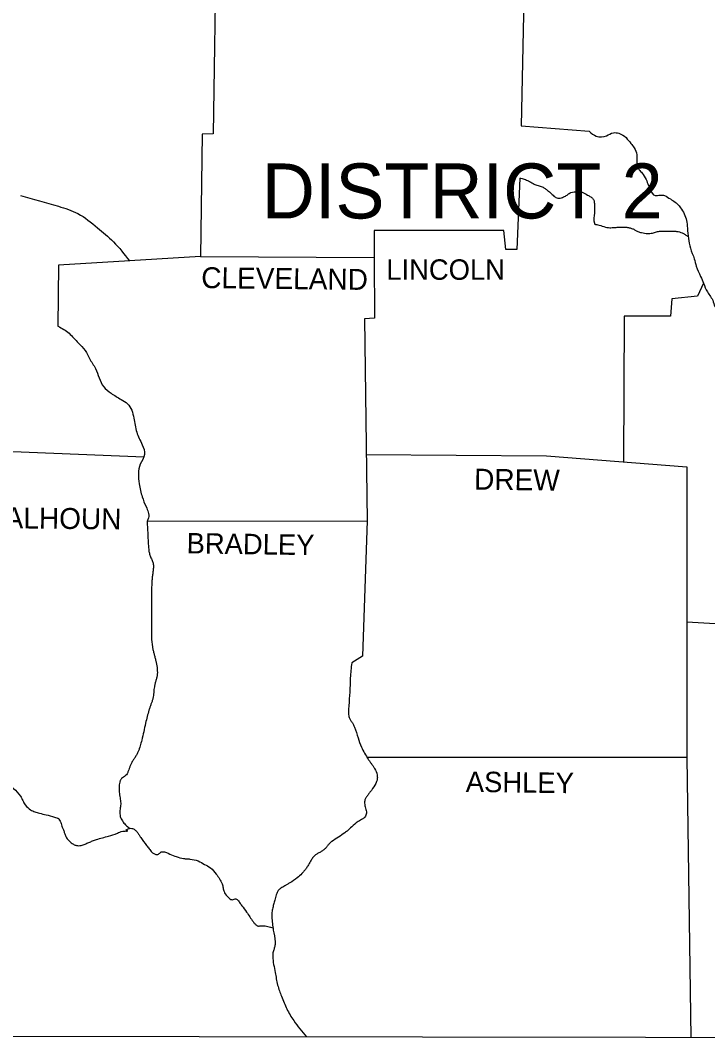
# Model space of a CAD drawing. Extents: x 1334737.7 to 1334827.2, y 402732.3 to 402753.5.
# Drawn here: x 1334764.914 to 1334766.509, y 402745.105 to 402747.469 of the extents above; entities that cross this region are included whole.
import ezdxf

# ---------------------------------------------------------------- set-up
doc = ezdxf.new("R2010")
doc.units = 0
doc.layers.add('Default', color=7, linetype='Continuous')

msp = doc.modelspace()

# ---------------------------------------------------------------- linework, layer by layer
at = {"layer": 'Default'}
for points in [[(1334765.3686, 402747.6648), (1334765.3618, 402747.2056), (1334765.3358, 402747.2045), (1334765.3324, 402746.9205)], [(1334766.0861, 402747.6676), (1334766.0767, 402747.2237), (1334766.234, 402747.2112)], [(1334766.0733, 402747.1027), (1334766.0665, 402746.9364), (1334766.0405, 402746.9364), (1334766.036, 402746.9805), (1334765.7351, 402746.9805), (1334765.7355, 402746.9183)], [(1334765.1677, 402746.9104), (1334765.0021, 402746.9002), (1334765.001, 402746.7588)], [(1334765.3324, 402746.9205), (1334765.167, 402746.9103)], [(1334765.3324, 402746.9205), (1334765.7355, 402746.9183)], [(1334765.7355, 402746.9183), (1334765.7362, 402746.7769), (1334765.7125, 402746.7758), (1334765.7193, 402746.3063)], [(1334766.4998, 402746.8583), (1334766.4862, 402746.8278), (1334766.4262, 402746.8221), (1334766.4229, 402746.7814), (1334766.3154, 402746.7814), (1334766.3143, 402746.4432)], [(1334764.3698, 402746.4862), (1334764.8381, 402746.4692), (1334765.2014, 402746.455)], [(1334765.7159, 402746.4602), (1334766.1355, 402746.4568), (1334766.4613, 402746.4319)], [(1334766.4613, 402746.4319), (1334766.4613, 402745.7555), (1334766.4704, 402745.1058)], [(1334765.208, 402746.3052), (1334765.7193, 402746.3063)], [(1334765.7193, 402746.3063), (1334765.708, 402745.9919), (1334765.6831, 402745.9761)], [(1334766.4613, 402746.0714), (1334766.6185, 402746.062), (1334766.6253, 402745.9964), (1334766.7622, 402746.0009), (1334766.7679, 402746.0564), (1334766.8102, 402746.0564)], [(1334762.7353, 402746.027), (1334762.7376, 402745.1119), (1334766.8832, 402745.1051)], [(1334765.7187, 402745.7566), (1334766.4613, 402745.7566)]]:
    msp.add_lwpolyline(points, dxfattribs=at)
for points in [[(1334766.234, 402747.2112), (1334766.2509, 402747.1999), (1334766.2747, 402747.2011), (1334766.2905, 402747.2078), (1334766.303, 402747.2067), (1334766.3199, 402747.1965), (1334766.3312, 402747.183), (1334766.3391, 402747.1728), (1334766.3448, 402747.1569), (1334766.3448, 402747.1422), (1334766.3505, 402747.1219), (1334766.3572, 402747.114), (1334766.3663, 402747.0993), (1334766.372, 402747.0857), (1334766.3753, 402747.0766), (1334766.3878, 402747.0619), (1334766.3991, 402747.0631), (1334766.4093, 402747.0619), (1334766.4229, 402747.054), (1334766.4432, 402747.0382), (1334766.4466, 402747.0337), (1334766.4602, 402747.0042), (1334766.4624, 402746.9861), (1334766.4647, 402746.9624), (1334766.4692, 402746.9398), (1334766.4783, 402746.9149), (1334766.4828, 402746.8979), (1334766.493, 402746.8742), (1334766.4998, 402746.8583), (1334766.5088, 402746.838), (1334766.5224, 402746.8153), (1334766.528, 402746.8018), (1334766.5473, 402746.8029), (1334766.5609, 402746.8086), (1334766.571, 402746.8176), (1334766.5835, 402746.8165), (1334766.597, 402746.812), (1334766.6151, 402746.8086), (1334766.6265, 402746.8153), (1334766.6321, 402746.8199), (1334766.6332, 402746.8301), (1334766.6434, 402746.8357), (1334766.6547, 402746.8278), (1334766.6672, 402746.8097), (1334766.6672, 402746.7984), (1334766.6627, 402746.7916), (1334766.648, 402746.7825), (1334766.6276, 402746.7758), (1334766.6219, 402746.7678), (1334766.6412, 402746.7588), (1334766.6717, 402746.7565), (1334766.6796, 402746.7633), (1334766.7, 402746.7577), (1334766.7079, 402746.7633), (1334766.7351, 402746.7622), (1334766.7475, 402746.7712), (1334766.7724, 402746.7701), (1334766.7803, 402746.7644), (1334766.7803, 402746.7543), (1334766.8007, 402746.7497), (1334766.8154, 402746.7531), (1334766.8346, 402746.7475), (1334766.8516, 402746.7384), (1334766.8606, 402746.726), (1334766.8719, 402746.7124), (1334766.8821, 402746.7158), (1334766.89, 402746.726), (1334766.907, 402746.7441), (1334766.907, 402746.7554), (1334766.9115, 402746.7633), (1334766.9183, 402746.778)], [(1334766.0733, 402747.1027), (1334766.0786, 402747.1016), (1334766.0837, 402747.1), (1334766.0937, 402747.0959), (1334766.0974, 402747.094), (1334766.1011, 402747.0919), (1334766.1047, 402747.0898), (1334766.1084, 402747.0879), (1334766.1132, 402747.0862), (1334766.1181, 402747.0848), (1334766.123, 402747.0833), (1334766.1276, 402747.0812), (1334766.134, 402747.0768), (1334766.1401, 402747.0721), (1334766.1443, 402747.0685), (1334766.1485, 402747.0646), (1334766.1526, 402747.0608), (1334766.1548, 402747.059), (1334766.157, 402747.0574), (1334766.1617, 402747.0558), (1334766.167, 402747.0561), (1334766.1724, 402747.0577), (1334766.1774, 402747.0597), (1334766.1811, 402747.0618), (1334766.1846, 402747.0644), (1334766.1881, 402747.0669), (1334766.1921, 402747.0687), (1334766.2068, 402747.071), (1334766.2181, 402747.0698), (1334766.2306, 402747.0631), (1334766.2379, 402747.0589), (1334766.2413, 402747.0563), (1334766.2428, 402747.0547), (1334766.2435, 402747.0539), (1334766.2441, 402747.0529), (1334766.2463, 402747.0456), (1334766.2464, 402747.0419), (1334766.2464, 402747.0382), (1334766.2464, 402747.0212), (1334766.2464, 402746.9975), (1334766.2472, 402746.9958), (1334766.2493, 402746.995), (1334766.2543, 402746.9941), (1334766.2684, 402746.9897), (1334766.2826, 402746.9873), (1334766.2874, 402746.9874), (1334766.2922, 402746.9877), (1334766.297, 402746.9881), (1334766.3018, 402746.9884), (1334766.3109, 402746.9886), (1334766.3199, 402746.9884), (1334766.3274, 402746.9873), (1334766.331, 402746.9863), (1334766.3346, 402746.985), (1334766.3378, 402746.9835), (1334766.3408, 402746.9815), (1334766.3438, 402746.9797), (1334766.3471, 402746.9782), (1334766.3561, 402746.976), (1334766.3697, 402746.9737), (1334766.381, 402746.9748), (1334766.3858, 402746.976), (1334766.3906, 402746.9775), (1334766.3954, 402746.9788), (1334766.4002, 402746.9794), (1334766.4115, 402746.9794), (1334766.4296, 402746.9794), (1334766.4353, 402746.979), (1334766.4381, 402746.9786), (1334766.441, 402746.9782), (1334766.453, 402746.9737), (1334766.4588, 402746.9702), (1334766.4643, 402746.9665)], [(1334764.9139, 402747.0619), (1334765.0021, 402747.037), (1334765.0474, 402747.0201), (1334765.0926, 402746.9873), (1334765.1299, 402746.9545), (1334765.167, 402746.9103)], [(1334765.001, 402746.7588), (1334765.027, 402746.7418), (1334765.0485, 402746.7192), (1334765.0643, 402746.7022), (1334765.0745, 402746.683), (1334765.0881, 402746.6604), (1334765.1073, 402746.6174), (1334765.1243, 402746.6027), (1334765.148, 402746.588), (1334765.1628, 402746.5778), (1334765.1775, 402746.545), (1334765.1842, 402746.5122), (1334765.1967, 402746.4828), (1334765.2023, 402746.4602), (1334765.1922, 402746.4376), (1334765.1899, 402746.3923), (1334765.1967, 402746.3618), (1334765.2057, 402746.3391), (1334765.2114, 402746.3131), (1334765.208, 402746.3052)], [(1334765.208, 402746.3052), (1334765.2089, 402746.2877), (1334765.2099, 402746.2701), (1334765.2125, 402746.2351), (1334765.2145, 402746.2265), (1334765.218, 402746.2181), (1334765.2213, 402746.2097), (1334765.2223, 402746.2055), (1334765.2227, 402746.2011), (1334765.2222, 402746.1921), (1334765.2211, 402746.1831), (1334765.22, 402746.174), (1334765.2193, 402746.165), (1334765.2182, 402746.1299), (1334765.2182, 402746.0982), (1334765.2182, 402746.0677), (1334765.2182, 402746.036), (1334765.2204, 402746.0134), (1334765.2221, 402746.0051), (1334765.2242, 402745.9969), (1334765.2264, 402745.9888), (1334765.2284, 402745.9806), (1334765.2311, 402745.9653), (1334765.2318, 402745.9576), (1334765.2318, 402745.95), (1334765.2306, 402745.9427), (1334765.2287, 402745.9353), (1334765.2266, 402745.928), (1334765.225, 402745.9206), (1334765.2241, 402745.9139), (1334765.2235, 402745.907), (1334765.2228, 402745.9002), (1334765.2216, 402745.8935), (1334765.2195, 402745.8866), (1334765.2171, 402745.8799), (1334765.2147, 402745.8732), (1334765.2125, 402745.8663), (1334765.2046, 402745.8358), (1334765.1956, 402745.7962), (1334765.1921, 402745.7831), (1334765.19, 402745.7766), (1334765.1876, 402745.7702), (1334765.1842, 402745.7631), (1334765.1801, 402745.7564), (1334765.1757, 402745.7498), (1334765.1718, 402745.743), (1334765.169, 402745.7369), (1334765.1666, 402745.7306), (1334765.1643, 402745.7243), (1334765.1616, 402745.7182), (1334765.1581, 402745.7139), (1334765.1534, 402745.7105), (1334765.1488, 402745.707), (1334765.147, 402745.7048), (1334765.1458, 402745.7023), (1334765.1433, 402745.6888), (1334765.1435, 402745.6752), (1334765.1442, 402745.669), (1334765.1453, 402745.6627), (1334765.1463, 402745.6565), (1334765.1469, 402745.6503), (1334765.1467, 402745.6446), (1334765.1458, 402745.639), (1334765.1449, 402745.6333), (1334765.1447, 402745.6277), (1334765.1467, 402745.6167), (1334765.1526, 402745.6062), (1334765.1563, 402745.6016), (1334765.1604, 402745.5972), (1334765.1687, 402745.5915)], [(1334765.6831, 402745.9761), (1334765.6797, 402745.941), (1334765.6786, 402745.9082), (1334765.6763, 402745.8765), (1334765.6757, 402745.8646), (1334765.6757, 402745.8587), (1334765.6763, 402745.8528), (1334765.6786, 402745.8459), (1334765.6824, 402745.8396), (1334765.6866, 402745.8333), (1334765.6899, 402745.8267), (1334765.6978, 402745.8019), (1334765.7057, 402745.7804), (1334765.7215, 402745.7521), (1334765.7251, 402745.7467), (1334765.7289, 402745.7414), (1334765.7327, 402745.7361), (1334765.7362, 402745.7306), (1334765.742, 402745.7154), (1334765.7425, 402745.7075), (1334765.7408, 402745.7001), (1334765.7317, 402745.6842), (1334765.7276, 402745.6782), (1334765.7232, 402745.6723), (1334765.7188, 402745.6664), (1334765.7148, 402745.6605), (1334765.7129, 402745.6501), (1334765.7153, 402745.6383), (1334765.7172, 402745.6268), (1334765.7136, 402745.6175), (1334765.7113, 402745.6155), (1334765.7088, 402745.6137), (1334765.7035, 402745.6105), (1334765.6982, 402745.6074), (1334765.6933, 402745.6039), (1334765.6805, 402745.5924), (1334765.674, 402745.5866), (1334765.6672, 402745.5813), (1334765.6525, 402745.5711), (1334765.6367, 402745.5609), (1334765.632, 402745.5569), (1334765.6279, 402745.5522), (1334765.624, 402745.5473), (1334765.6197, 402745.5428), (1334765.6137, 402745.5384), (1334765.6071, 402745.5346), (1334765.6006, 402745.5307), (1334765.5949, 402745.5259), (1334765.5898, 402745.5192), (1334765.5856, 402745.5119), (1334765.5815, 402745.5045), (1334765.5768, 402745.4976), (1334765.572, 402745.4918), (1334765.5672, 402745.4862), (1334765.5564, 402745.4761), (1334765.5394, 402745.4648), (1334765.5335, 402745.4612), (1334765.5275, 402745.4577), (1334765.5186, 402745.4522), (1334765.5157, 402745.4501), (1334765.5115, 402745.4455), (1334765.5089, 402745.4398), (1334765.5055, 402745.4275), (1334765.5025, 402745.417), (1334765.4998, 402745.4066), (1334765.4979, 402745.3961), (1334765.4976, 402745.3856), (1334765.4989, 402745.3703), (1334765.501, 402745.3551), (1334765.5055, 402745.3279), (1334765.505, 402745.3194), (1334765.5027, 402745.311), (1334765.5003, 402745.3025), (1334765.4998, 402745.294), (1334765.5055, 402745.2567), (1334765.5111, 402745.2272), (1334765.5202, 402745.2012), (1334765.5326, 402745.1718), (1334765.54, 402745.158), (1334765.5485, 402745.1447), (1334765.5627, 402745.1254), (1334765.5783, 402745.1072)], [(1334764.5553, 402745.7148), (1334764.5734, 402745.7272), (1334764.5904, 402745.734), (1334764.5988, 402745.7325), (1334764.6031, 402745.7315), (1334764.6074, 402745.7306), (1334764.6255, 402745.7283), (1334764.6294, 402745.7285), (1334764.6334, 402745.7293), (1334764.6373, 402745.7302), (1334764.6413, 402745.7306), (1334764.6617, 402745.7272), (1334764.6662, 402745.7249), (1334764.6703, 402745.7222), (1334764.6744, 402745.7195), (1334764.6786, 402745.717), (1334764.688, 402745.7119), (1334764.6978, 402745.7091), (1334764.7171, 402745.7091), (1334764.734, 402745.7091), (1334764.7381, 402745.7077), (1334764.7415, 402745.7044), (1334764.7449, 402745.701), (1334764.7487, 402745.6989), (1334764.7554, 402745.698), (1334764.7624, 402745.6977), (1334764.7693, 402745.6984), (1334764.7759, 402745.7001), (1334764.7816, 402745.7022), (1334764.7872, 402745.7046), (1334764.7928, 402745.707), (1334764.7985, 402745.7091), (1334764.8211, 402745.7159), (1334764.8288, 402745.7182), (1334764.8366, 402745.7202), (1334764.8444, 402745.7209), (1334764.8481, 402745.7205), (1334764.8517, 402745.7193), (1334764.8658, 402745.7106), (1334764.8788, 402745.7001), (1334764.8886, 402745.6923), (1334764.8981, 402745.6842), (1334764.9139, 402745.6661), (1334764.917, 402745.6612), (1334764.9196, 402745.656), (1334764.9221, 402745.6508), (1334764.9252, 402745.6458), (1334764.9377, 402745.6345), (1334764.9426, 402745.6319), (1334764.9476, 402745.6298), (1334764.958, 402745.6265), (1334764.9738, 402745.6231), (1334764.9931, 402745.6175), (1334764.9985, 402745.616), (1334765.0011, 402745.6148), (1334765.0033, 402745.613), (1334765.0065, 402745.6079), (1334765.0086, 402745.6024), (1334765.0103, 402745.5969), (1334765.0123, 402745.5915), (1334765.0139, 402745.5877), (1334765.0152, 402745.584), (1334765.0178, 402745.5766), (1334765.0213, 402745.5693), (1334765.0238, 402745.5657), (1334765.0253, 402745.5639), (1334765.027, 402745.5621), (1334765.0338, 402745.5564), (1334765.041, 402745.5527), (1334765.0482, 402745.5511), (1334765.0553, 402745.5519), (1334765.064, 402745.5549), (1334765.0728, 402745.5586), (1334765.0815, 402745.5623), (1334765.0904, 402745.5655), (1334765.1186, 402745.5734), (1334765.139, 402745.5802), (1334765.1514, 402745.5847), (1334765.1542, 402745.5852), (1334765.1571, 402745.5853), (1334765.16, 402745.5853), (1334765.1628, 402745.5858), (1334765.1629, 402745.586), (1334765.1626, 402745.5863), (1334765.1611, 402745.5869), (1334765.1596, 402745.5875), (1334765.1592, 402745.5878), (1334765.1594, 402745.5881), (1334765.1626, 402745.5896), (1334765.1661, 402745.5909), (1334765.1729, 402745.5915), (1334765.1762, 402745.5902), (1334765.1796, 402745.5881), (1334765.1854, 402745.5824), (1334765.1875, 402745.5793), (1334765.1894, 402745.5761), (1334765.1912, 402745.573), (1334765.1933, 402745.57), (1334765.2069, 402745.5519), (1334765.2128, 402745.5439), (1334765.2159, 402745.54), (1334765.2193, 402745.536), (1334765.2221, 402745.5337), (1334765.2253, 402745.5321), (1334765.2286, 402745.531), (1334765.2318, 402745.5304), (1334765.2348, 402745.5314), (1334765.2379, 402745.5341), (1334765.241, 402745.5366), (1334765.2442, 402745.5372), (1334765.2612, 402745.5315), (1334765.2759, 402745.5259), (1334765.2928, 402745.5213), (1334765.2965, 402745.5209), (1334765.3002, 402745.5207), (1334765.3039, 402745.5206), (1334765.3075, 402745.5202), (1334765.3268, 402745.5157), (1334765.3415, 402745.5078), (1334765.355, 402745.4999), (1334765.3686, 402745.4851), (1334765.3822, 402745.4625), (1334765.3837, 402745.4582), (1334765.3845, 402745.4536), (1334765.3853, 402745.4489), (1334765.3867, 402745.4444), (1334765.3934, 402745.4343), (1334765.3978, 402745.4301), (1334765.4026, 402745.4263), (1334765.4061, 402745.4256), (1334765.4103, 402745.4267), (1334765.4143, 402745.4276), (1334765.4173, 402745.4263), (1334765.4228, 402745.4191), (1334765.4282, 402745.4117), (1334765.4388, 402745.3969), (1334765.4467, 402745.3856), (1334765.454, 402745.3747), (1334765.4583, 402745.3697), (1334765.4608, 402745.3674), (1334765.4636, 402745.3652), (1334765.4666, 402745.3643), (1334765.4698, 402745.3646), (1334765.473, 402745.3652), (1334765.4761, 402745.3652), (1334765.5002, 402745.3606)]]:
    msp.add_spline(points, degree=3, dxfattribs=at)

# ---------------------------------------------------------------- texts
for s, height, p in [('DISTRICT 2', 0.12781, (1334765.4743, 402747.0087)), ('LINCOLN', 0.04751, (1334765.7634, 402746.8662))]:
    msp.add_text(s, height=height, dxfattribs=at).set_placement(p)
for s, height, rotation, p in [('CLEVELAND', 0.04865, 359.3377, (1334765.3336, 402746.847)), ('DREW', 0.04863, 359.2258, (1334765.967, 402746.3787)), ('CALHOUN', 0.04865, 359.3634, (1334764.8302, 402746.2894)), ('BRADLEY', 0.0475, 359.1449, (1334765.2996, 402746.2306)), ('ASHLEY', 0.04751, 359.2361, (1334765.9478, 402745.6763))]:
    msp.add_text(s, height=height, rotation=rotation, dxfattribs=at).set_placement(p)

doc.saveas('drawing.dxf')
